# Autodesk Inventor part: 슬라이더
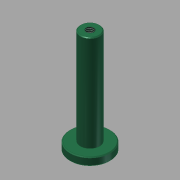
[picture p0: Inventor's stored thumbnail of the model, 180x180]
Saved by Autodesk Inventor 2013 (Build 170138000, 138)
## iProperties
Created: 2016-02
Part Number: 슬라이더
Material: 스테인리스강
Document SubType Name: Modeling
Designer: mduedu
Density: 8.08 g/cm^3
Mass: 72.5507 g
Surface Area: 37.669 cm^2
Volume: 8.97904 cm^3
Author: mduedu
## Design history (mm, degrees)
sketch "스케치1"
  geometry: C1 r 12.5 at (0, 0); 1 further point
  constraints: 1 centre point, 1 coincident
  dimensions: "d0" = 25 diameter of C1
extrude "돌출1" new body sketch "스케치1" distance "d1" = 5; taper "d2" = 0 deg
sketch "스케치2"
  geometry: C1 r 6 at (0, 0); 1 further point
  constraints: 1 centre point, 1 coincident
  dimensions: "d3" = 12 diameter of C1
extrude "돌출2" join sketch "스케치2" distance "d4" = 60; taper "d5" = 0 deg
chamfer "모따기1" distance "d6" = 0.5; stored, may be unused: second distance "d7" = 2, angle "d8" = 45 deg
hole "구멍1" diameter "d11" = 4.917; stored, may be unused: countersink angle "d15" = 90 deg, drill point angle "d17" = 118 deg; dims "d9" = 10, "d10" = 10, "d12" = 10, "d13" = 4, "d14" = 2, "d16" = 12
chamfer "모따기2" distance "d18" = 0.5; stored, may be unused: second distance "d19" = 2, angle "d20" = 45 deg
node "솔리드1"
